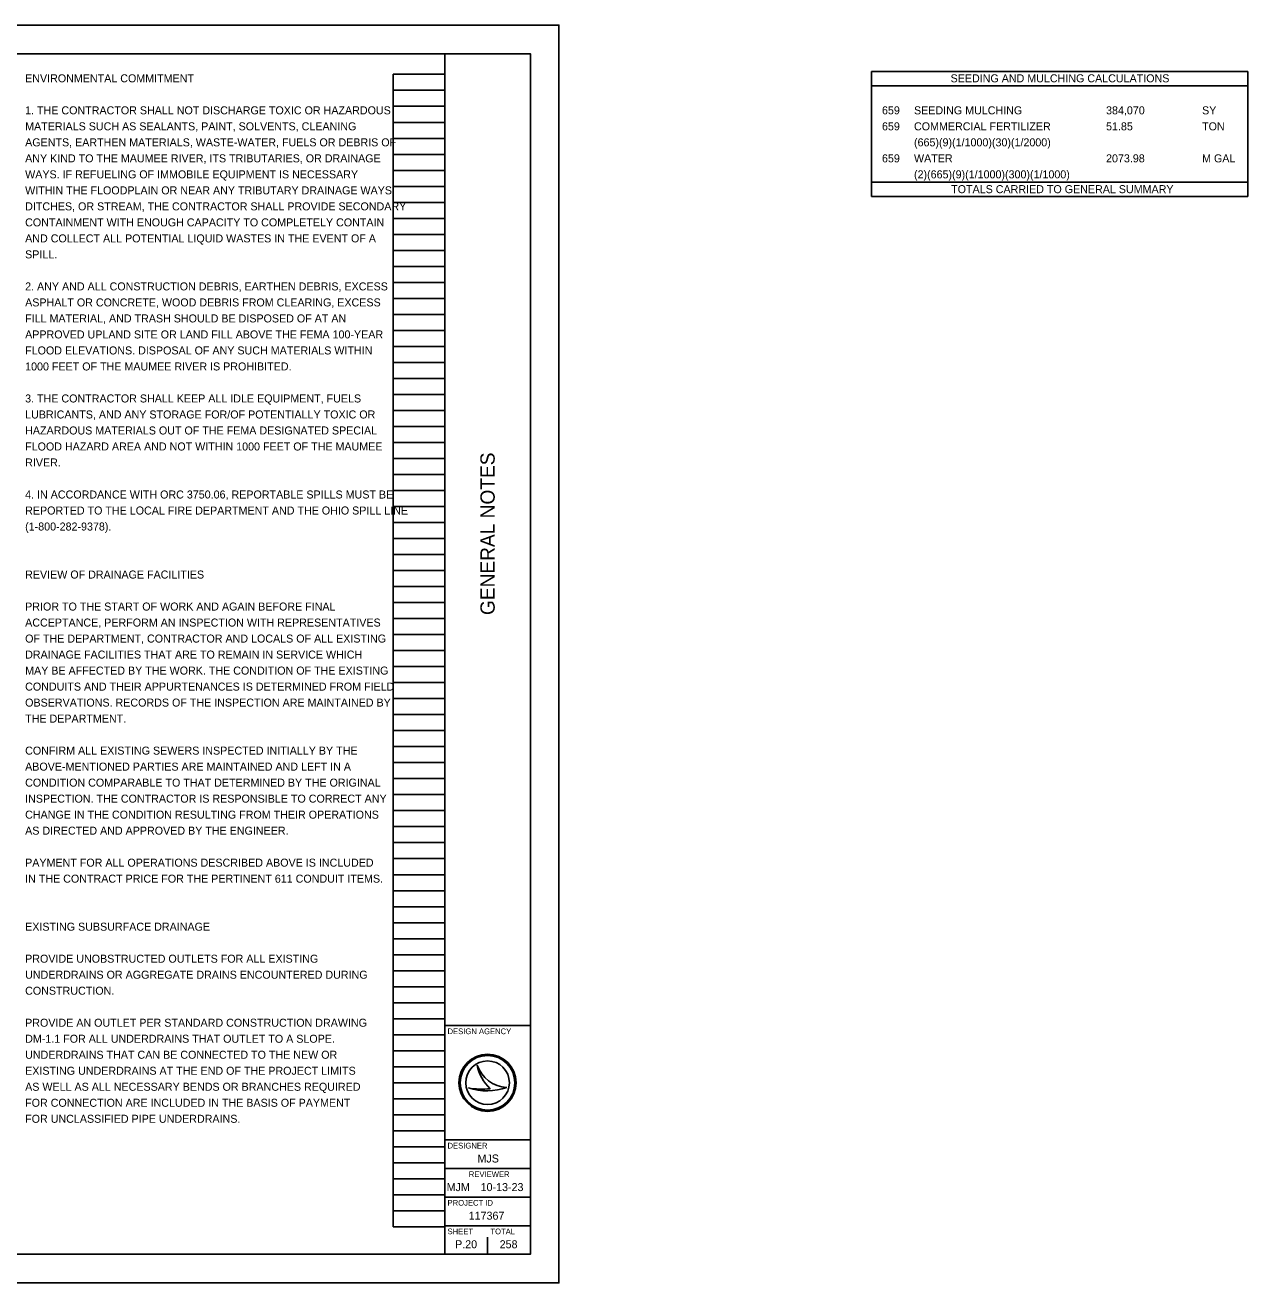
# Model space of a CAD drawing. Extents: x 0 to 46.1, y 0 to 22.
# Drawn here: x 24.66 to 46.05, y 0 to 22 of the extents above; entities that cross this region are included whole.
import ezdxf

# ---------------------------------------------------------------- set-up
doc = ezdxf.new("R2010")
doc.units = 0
for name, color, linetype in [('SH_Border', 7, 'Continuous'), ('SH_Cut_Line', 7, 'Continuous'), ('SH_Data', 7, 'Continuous'), ('SH_Text', 7, 'Continuous')]:
    doc.layers.add(name, color=color, linetype=linetype)

msp = doc.modelspace()

# ---------------------------------------------------------------- linework, layer by layer
at = {"layer": 'SH_Border'}
for p, q in [((32, 0.5), (32, 21.5)), ((32, 4.5), (33.5, 4.5)), ((32, 2.5), (33.5, 2.5)), ((32, 2), (33.5, 2)), ((32, 1.5), (33.5, 1.5)), ((32, 1), (33.5, 1))]:
    msp.add_line(p, q, dxfattribs=at)
msp.add_lwpolyline([(1.5, 21.5), (33.5, 21.5), (33.5, 0.5), (1.5, 0.5)], close=True, dxfattribs=at)
at = {"layer": 'SH_Cut_Line'}
msp.add_lwpolyline([(0, 0), (34, 0), (34, 22), (0, 22)], close=True, dxfattribs=at)
at = {"layer": 'SH_Data'}
for p, q in [((31.1, 0.98), (31.1, 21.14)), ((31.1, 21.14), (32, 21.14)), ((32, 0.98), (32, 21.14)), ((31.1, 20.86), (32, 20.86)), ((31.1, 20.58), (32, 20.58)), ((31.1, 20.3), (32, 20.3)), ((31.1, 20.02), (32, 20.02)), ((31.1, 19.74), (32, 19.74)), ((31.1, 19.46), (32, 19.46)), ((31.1, 19.18), (32, 19.18)), ((31.1, 18.9), (32, 18.9)), ((31.1, 18.62), (32, 18.62)), ((31.1, 18.34), (32, 18.34)), ((31.1, 18.06), (32, 18.06)), ((31.1, 17.78), (32, 17.78)), ((31.1, 17.5), (32, 17.5)), ((31.1, 17.22), (32, 17.22)), ((31.1, 16.94), (32, 16.94)), ((31.1, 16.66), (32, 16.66)), ((31.1, 16.38), (32, 16.38)), ((31.1, 16.1), (32, 16.1)), ((31.1, 15.82), (32, 15.82)), ((31.1, 15.54), (32, 15.54)), ((31.1, 15.26), (32, 15.26)), ((31.1, 14.98), (32, 14.98)), ((31.1, 14.7), (32, 14.7)), ((31.1, 14.42), (32, 14.42)), ((31.1, 14.14), (32, 14.14)), ((31.1, 13.86), (32, 13.86)), ((31.1, 13.58), (32, 13.58)), ((31.1, 13.3), (32, 13.3)), ((31.1, 13.02), (32, 13.02)), ((31.1, 12.74), (32, 12.74)), ((31.1, 12.46), (32, 12.46)), ((31.1, 12.18), (32, 12.18)), ((31.1, 11.9), (32, 11.9)), ((31.1, 11.62), (32, 11.62)), ((31.1, 11.34), (32, 11.34)), ((31.1, 11.06), (32, 11.06)), ((31.1, 10.78), (32, 10.78)), ((31.1, 10.5), (32, 10.5)), ((31.1, 10.22), (32, 10.22)), ((31.1, 9.94), (32, 9.94)), ((31.1, 9.66), (32, 9.66)), ((31.1, 9.38), (32, 9.38)), ((31.1, 9.1), (32, 9.1)), ((31.1, 8.82), (32, 8.82)), ((31.1, 8.54), (32, 8.54)), ((31.1, 8.26), (32, 8.26)), ((31.1, 7.98), (32, 7.98)), ((31.1, 7.7), (32, 7.7)), ((31.1, 7.42), (32, 7.42)), ((31.1, 7.14), (32, 7.14)), ((31.1, 6.86), (32, 6.86)), ((31.1, 6.58), (32, 6.58)), ((31.1, 6.3), (32, 6.3)), ((31.1, 6.02), (32, 6.02)), ((31.1, 5.74), (32, 5.74)), ((31.1, 5.46), (32, 5.46)), ((31.1, 5.18), (32, 5.18)), ((31.1, 4.9), (32, 4.9)), ((31.1, 4.62), (32, 4.62)), ((31.1, 4.34), (32, 4.34)), ((31.1, 4.06), (32, 4.06)), ((31.1, 3.78), (32, 3.78)), ((32.567, 3.81), (32.567, 3.81)), ((31.1, 3.5), (32, 3.5)), ((32.417, 3.41), (32.417, 3.41)), ((32.75, 3.5), (32.75, 3.5)), ((33.087, 3.419), (33.087, 3.419)), ((31.1, 3.22), (32, 3.22)), ((31.1, 2.94), (32, 2.94)), ((31.1, 2.66), (32, 2.66)), ((31.1, 2.38), (32, 2.38)), ((31.1, 2.1), (32, 2.1)), ((31.1, 1.82), (32, 1.82)), ((31.1, 1.54), (32, 1.54)), ((31.1, 1.26), (32, 1.26)), ((31.1, 0.98), (32, 0.98)), ((32.375, 0.675), (32.375, 0.675)), ((32.75, 0.5), (32.75, 0.8))]:
    msp.add_line(p, q, dxfattribs=at)
for radius in [0.5, 0.477, 0.477, 0.382]:
    msp.add_circle((32.75, 3.5), radius, dxfattribs=at)
for centre, radius, start, end in [((33.116, 3.998), 0.58, 198.9257, 198.9319), ((33.347, 3.97), 0.796, 191.6379, 191.6421), ((33.116, 3.998), 0.58, 198.9319, 267.1657), ((33.347, 3.97), 0.796, 191.6421, 226.0947), ((32.739, 4.37), 1.013, 251.4576, 290.0832), ((32.648, 4.654), 1.266, 259.4964, 259.4995), ((32.739, 4.37), 1.013, 251.4527, 251.4576), ((32.648, 4.654), 1.266, 259.4995, 276.6672)]:
    msp.add_arc(centre, radius, start, end, dxfattribs=at)
at = {"layer": 'SH_Text'}
for p, q in [((39.47, 21.191), (39.47, 20.94)), ((46.052, 21.191), (39.47, 21.191)), ((39.47, 21.191), (39.47, 19)), ((46.052, 20.94), (46.052, 21.191)), ((46.052, 19), (46.052, 21.191)), ((39.47, 20.94), (46.052, 20.94)), ((46.052, 19.251), (39.47, 19.251)), ((39.47, 19), (46.052, 19))]:
    msp.add_line(p, q, dxfattribs=at)

# ---------------------------------------------------------------- texts
at = {"layer": 'SH_Data'}
msp.add_text('GENERAL NOTES', height=0.25, rotation=90, dxfattribs=at).set_placement((32.875, 11.682))
for s, height, p in [('DESIGN AGENCY', 0.1, (32.05, 4.35)), ('DESIGNER', 0.1, (32.05, 2.35)), ('MJS', 0.14, (32.574, 2.105)), ('REVIEWER', 0.1, (32.422, 1.85)), ('MJM', 0.14, (32.035, 1.605)), ('10-13-23', 0.14, (32.629, 1.605)), ('PROJECT ID', 0.1, (32.05, 1.35)), ('117367', 0.14, (32.42, 1.105)), ('SHEET', 0.1, (32.05, 0.85)), ('TOTAL', 0.1, (32.8, 0.85)), ('P.20', 0.14, (32.182, 0.605)), ('258', 0.14, (32.962, 0.605))]:
    msp.add_text(s, height=height, dxfattribs=at).set_placement(p)
at = {"layer": 'SH_Text'}
for s, p in [('ENVIRONMENTAL COMMITMENT', (24.66, 21)), ('SEEDING AND MULCHING CALCULATIONS', (40.851, 21)), ('1. THE CONTRACTOR SHALL NOT DISCHARGE TOXIC OR HAZARDOUS ', (24.66, 20.44)), ('659', (39.651, 20.44)), ('SEEDING MULCHING', (40.211, 20.44)), ('384,070', (43.571, 20.44)), ('SY', (45.251, 20.44)), ('MATERIALS SUCH AS SEALANTS, PAINT, SOLVENTS, CLEANING', (24.66, 20.16)), ('659', (39.651, 20.16)), ('COMMERCIAL FERTILIZER', (40.211, 20.16)), ('51.85', (43.571, 20.16)), ('TON', (45.251, 20.16)), ('AGENTS, EARTHEN MATERIALS, WASTE-WATER, FUELS OR DEBRIS OF', (24.66, 19.88)), ('(665)(9)(1/1000)(30)(1/2000)', (40.211, 19.88)), ('ANY KIND TO THE MAUMEE RIVER, ITS TRIBUTARIES, OR DRAINAGE', (24.66, 19.6)), ('659', (39.651, 19.6)), ('WATER', (40.211, 19.6)), ('2073.98', (43.571, 19.6)), ('M GAL', (45.251, 19.6)), ('WAYS. IF REFUELING OF IMMOBILE EQUIPMENT IS NECESSARY', (24.66, 19.32)), ('(2)(665)(9)(1/1000)(300)(1/1000)', (40.211, 19.32)), ('WITHIN THE FLOODPLAIN OR NEAR ANY TRIBUTARY DRAINAGE WAYS,', (24.66, 19.04)), ('TOTALS CARRIED TO GENERAL SUMMARY', (40.861, 19.061)), ('DITCHES, OR STREAM, THE CONTRACTOR SHALL PROVIDE SECONDARY', (24.66, 18.76)), ('CONTAINMENT WITH ENOUGH CAPACITY TO COMPLETELY CONTAIN', (24.66, 18.48)), ('AND COLLECT ALL POTENTIAL LIQUID WASTES IN THE EVENT OF A ', (24.66, 18.2)), ('SPILL. ', (24.66, 17.92)), ('2. ANY AND ALL CONSTRUCTION DEBRIS, EARTHEN DEBRIS, EXCESS ', (24.66, 17.36)), ('ASPHALT OR CONCRETE, WOOD DEBRIS FROM CLEARING, EXCESS', (24.66, 17.08)), ('FILL MATERIAL, AND TRASH SHOULD BE DISPOSED OF AT AN', (24.66, 16.8)), ('APPROVED UPLAND SITE OR LAND FILL ABOVE THE FEMA 100-YEAR', (24.66, 16.52)), ('FLOOD ELEVATIONS. DISPOSAL OF ANY SUCH MATERIALS WITHIN', (24.66, 16.24)), ('1000 FEET OF THE MAUMEE RIVER IS PROHIBITED.', (24.66, 15.96)), ('3. THE CONTRACTOR SHALL KEEP ALL IDLE EQUIPMENT, FUELS', (24.66, 15.4)), ('LUBRICANTS, AND ANY STORAGE FOR/OF POTENTIALLY TOXIC OR', (24.66, 15.12)), ('HAZARDOUS MATERIALS OUT OF THE FEMA DESIGNATED SPECIAL', (24.66, 14.84)), ('FLOOD HAZARD AREA AND NOT WITHIN 1000 FEET OF THE MAUMEE', (24.66, 14.56)), ('RIVER.', (24.66, 14.28)), ('4. IN ACCORDANCE WITH ORC 3750.06, REPORTABLE SPILLS MUST BE', (24.66, 13.72)), ('REPORTED TO THE LOCAL FIRE DEPARTMENT AND THE OHIO SPILL LINE', (24.66, 13.44)), ('(1-800-282-9378).', (24.66, 13.16)), ('REVIEW OF DRAINAGE FACILITIES', (24.66, 12.32)), ('PRIOR TO THE START OF WORK AND AGAIN BEFORE FINAL', (24.66, 11.76)), ('ACCEPTANCE, PERFORM AN INSPECTION WITH REPRESENTATIVES', (24.66, 11.48)), ('OF THE DEPARTMENT, CONTRACTOR AND LOCALS OF ALL EXISTING', (24.66, 11.2)), ('DRAINAGE FACILITIES THAT ARE TO REMAIN IN SERVICE WHICH', (24.66, 10.92)), ('MAY BE AFFECTED BY THE WORK. THE CONDITION OF THE EXISTING', (24.66, 10.64)), ('CONDUITS AND THEIR APPURTENANCES IS DETERMINED FROM FIELD', (24.66, 10.36)), ('OBSERVATIONS. RECORDS OF THE INSPECTION ARE MAINTAINED BY', (24.66, 10.08)), ('THE DEPARTMENT.', (24.66, 9.8)), ('CONFIRM ALL EXISTING SEWERS INSPECTED INITIALLY BY THE', (24.66, 9.24)), ('ABOVE-MENTIONED PARTIES ARE MAINTAINED AND LEFT IN A', (24.66, 8.96)), ('CONDITION COMPARABLE TO THAT DETERMINED BY THE ORIGINAL', (24.66, 8.68)), ('INSPECTION. THE CONTRACTOR IS RESPONSIBLE TO CORRECT ANY', (24.66, 8.4)), ('CHANGE IN THE CONDITION RESULTING FROM THEIR OPERATIONS', (24.66, 8.12)), ('AS DIRECTED AND APPROVED BY THE ENGINEER.', (24.66, 7.84)), ('PAYMENT FOR ALL OPERATIONS DESCRIBED ABOVE IS INCLUDED', (24.66, 7.28)), ('IN THE CONTRACT PRICE FOR THE PERTINENT 611 CONDUIT ITEMS.', (24.66, 7)), ('EXISTING SUBSURFACE DRAINAGE', (24.66, 6.16)), ('PROVIDE UNOBSTRUCTED OUTLETS FOR ALL EXISTING', (24.66, 5.6)), ('UNDERDRAINS OR AGGREGATE DRAINS ENCOUNTERED DURING', (24.66, 5.32)), ('CONSTRUCTION.', (24.66, 5.04)), ('PROVIDE AN OUTLET PER STANDARD CONSTRUCTION DRAWING', (24.66, 4.48)), ('DM-1.1 FOR ALL UNDERDRAINS THAT OUTLET TO A SLOPE.', (24.66, 4.2)), ('UNDERDRAINS THAT CAN BE CONNECTED TO THE NEW OR', (24.66, 3.92)), ('EXISTING UNDERDRAINS AT THE END OF THE PROJECT LIMITS', (24.66, 3.64)), ('AS WELL AS ALL NECESSARY BENDS OR BRANCHES REQUIRED', (24.66, 3.36)), ('FOR CONNECTION ARE INCLUDED IN THE BASIS OF PAYMENT', (24.66, 3.08)), ('FOR UNCLASSIFIED PIPE UNDERDRAINS.', (24.66, 2.8))]:
    msp.add_text(s, height=0.14, dxfattribs=at).set_placement(p)

doc.saveas('drawing.dxf')
